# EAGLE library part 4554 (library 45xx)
MULTIPLEXER
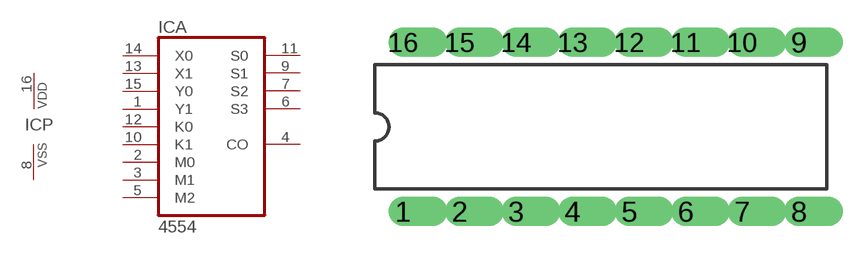
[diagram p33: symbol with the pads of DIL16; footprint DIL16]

Designator prefix IC; gates A=4554 P=PWRN

## 4554N  [DIL16]
1  A:Y1  in
2  A:M0  in
3  A:M1  in
4  A:CO  out
5  A:M2  in
6  A:S3  out
7  A:S2  out
8  P:VSS  pwr
9  A:S1  out
10  A:K1  in
11  A:S0  out
12  A:K0  in
13  A:X1  in
14  A:X0  in
15  A:Y0  in
16  P:VDD  pwr

## Footprint DIL16 (pad centres in mm)
Dual In Line
drill 0.813 offset: 1 -8.89,-3.81; 2 -6.35,-3.81; 3 -3.81,-3.81; 4 -1.27,-3.81; 5 1.27,-3.81; 6 3.81,-3.81; 7 6.35,-3.81; 8 8.89,-3.81; 9 8.89,3.81; 10 6.35,3.81; 11 3.81,3.81; 12 1.27,3.81; 13 -1.27,3.81; 14 -3.81,3.81; 15 -6.35,3.81; 16 -8.89,3.81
